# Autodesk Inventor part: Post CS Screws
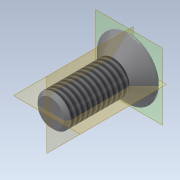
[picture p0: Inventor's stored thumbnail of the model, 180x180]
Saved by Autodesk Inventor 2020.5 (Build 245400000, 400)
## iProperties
LastFilename: FCG_Part.ipt
DataBaseUnit: MM
Created: 2018-01
Part Number: Post CS Screws
Material: 250 Grade
Document SubType Name: Modeling
Designer: A. Bennett
Density: 8.03824 g/cm^3
Appearance: Zinc Plating
Description: FHSS: M5 X 12 LG 'BLACK'
Stock Number: FHSS05012M
Mass: 2.20751 g
Surface Area: 3.30211 cm^2
Volume: 0.274626 cm^3
Author: A. Bennett
Revision Number: -
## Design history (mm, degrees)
sketch "Sketch10"
  geometry: L1 (0, -3.131)-(0, -12); L2 (0, -12)-(2.5, -12); L3 (2.5, -12)-(2.5, -2.45); L4 (2.5, -2.45)-(4.65, -0.3); L5 (4.597, 0)-(1.55, 0); L6 (1.55, 0)-(1.55, -2.2); L7 (1.55, -2.2)-(0, -3.131); L8 (0, 0)-(1.55, 0); L9 (0, 0)-(0, -3.131) reference; L10 (4.65, -0.3)-(4.597, 0)
  constraints: 20 end point, 3 perpendicular, 3 vertical, 1 horizontal, 1 parallel
  dimensions: "d26" = 12 distance between parallel lines of L8 L2; "d27" = 5 diameter of L3 L1; "d28" = 45 deg angle of L1 L4; "d29" = 59 deg angle of L1 L7; "d30" = 3.1 diameter of L6 L1; "d31" = 2.2 distance of L5.end L6.end; "d32" = 9.3 diameter of L4.end L1; "d33" = 0.3 distance from line of L4.end L5; "d35" = 100 deg angle of L5 L10
revolve "Revolution1" sketch "Sketch10" stored, may be unused: angle "d25" = 90 deg
chamfer "Chamfer1" distance "d36" = 0.5; stored, may be unused: second distance "d37" = 2, angle "d38" = 45 deg
chamfer "Chamfer2" distance "d39" = 0.25; stored, may be unused: second distance "d40" = 2, angle "d41" = 45 deg
sketch "Sketch11"
  geometry: L1 (-1.732, 0)-(-0.866, 1.5); L2 (-0.866, 1.5)-(0.866, 1.5); L3 (0.866, 1.5)-(1.732, 0); L4 (1.732, 0)-(0.866, -1.5); L5 (0.866, -1.5)-(-0.866, -1.5); L6 (-0.866, -1.5)-(-1.732, 0); 2 further points
  constraints: 12 end point, 1 coincident, 13 other
  dimensions: "d42" = 3 distance between parallel lines of L6 L3
extrude "Extrusion7" cut sketch "Sketch11" distance "d43" = 2.2; taper "d44" = 0 deg
fillet "Fillet2" dims "d45" = 0.1
thread "Thread1" dims "d46" = 10, "d47" = 0
body "Solid7"
other parameters: "OD" = 1 [user parameter], "OAL" = 1 [user parameter]
